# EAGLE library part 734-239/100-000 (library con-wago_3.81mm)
Serie 734, Stiftleiste (für Leiterplatten) Einpressstift 0,6 x 0,6 mm / Series 734, Male header (for PCBs) Press-in pin 0.6 x 0.6 mm Polzahl / Pole No.: 9 Rastermaß / Pitch: 3.81 mm Bemessungsspannung / Rated Voltage: 160 V Nennstrom / Nominal Current: 8 A Farbe / Color: orange / orange Stand: 01.01.2012. Die jeweils aktuellen Daten zu diesem Artikel finden Sie in unserem Produktkatalog, den Sie unter www.wago.com einsehen können. As of: 01/01/2012. Please find the newest data for this article in our product catalogue, which can be viewed under www.wago.com.
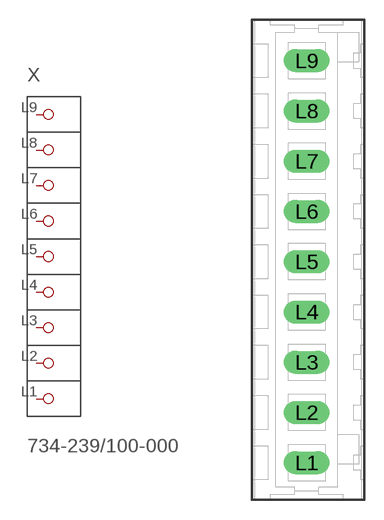
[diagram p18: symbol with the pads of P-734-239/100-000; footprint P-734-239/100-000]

Designator prefix X

## 734-239/100-000  [P-734-239/100-000]
L1  P1
L2  P2
L3  P3
L4  P4
L5  P5
L6  P6
L7  P7
L8  P8
L9  P9

## Footprint P-734-239/100-000 (pad centres in mm)
drill 1.15 long: L1 -0.1,-15.39; L2 -0.1,-11.58; L3 -0.1,-7.77; L4 -0.1,-3.96; L5 -0.1,-0.15; L6 -0.1,3.66; L7 -0.1,7.47; L8 -0.1,11.28; L9 -0.1,15.09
